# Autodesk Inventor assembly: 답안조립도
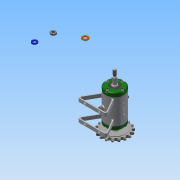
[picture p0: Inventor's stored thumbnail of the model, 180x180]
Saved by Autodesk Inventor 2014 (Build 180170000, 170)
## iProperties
Created: 2016-03
Part Number: 답안조립도
Document SubType Name: Assembly
Designer: 406-16
Author: 406-16
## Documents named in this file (16)
- C:\Users\406-16\Desktop\460307V1011\답안조립도.iam
- C:\Users\406-16\Desktop\460307V1011\본체1.ipt
- C:\Users\406-16\Desktop\460307V1011\축.ipt
- C:\Users\406-16\Desktop\460307V1011\베어링 15 x 32 x 9.ipt
- C:\Users\406-16\Desktop\460307V1011\V벨트풀리.ipt
- C:\Users\406-16\Desktop\460307V1011\키 3 x 3 x 12.ipt
- C:\Users\406-16\Desktop\460307V1011\스프로킷.ipt
- C:\Users\406-16\Desktop\460307V1011\커버.ipt
- C:\Users\406-16\Desktop\460307V1011\니플 M 6 x 0.75.ipt
- C:\Users\406-16\Desktop\460307V1011\너트 M 8.ipt
- C:\Users\406-16\Desktop\460307V1011\스프링와셔 8.ipt
- C:\Users\406-16\Desktop\460307V1011\와셔 6x11.5.ipt
- C:\Users\406-16\Desktop\460307V1011\오일 실 15 25 7.ipt
- C:\Users\406-16\Desktop\460307V1011\볼트 M4 x 12.ipt
- C:\Users\406-16\Desktop\460307V1011\볼트 M 6 x 8.ipt
- C:\Users\406-16\Desktop\460307V1011\와셔 8x17.ipt
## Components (11 placed, 3 different names)
1. KS B 2023 6002 - 15 x 32 x 9:1
2. KS B 2023 6002 - 15 x 32 x 9:2
3. V벨트풀리:1 — 각도:5
4. ISO 4762 M4 x 12:1
5. ISO 4762 M4 x 12:2
6. ISO 4762 M4 x 12:3
7. ISO 4762 M4 x 12:4
8. ISO 4762 M4 x 12:5
9. ISO 4762 M4 x 12:6
10. ISO 4762 M4 x 12:7
11. ISO 4762 M4 x 12:8
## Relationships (1: Angle 1)
- 각도:5 [Angle]: V벨트풀리:1
